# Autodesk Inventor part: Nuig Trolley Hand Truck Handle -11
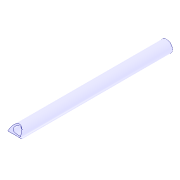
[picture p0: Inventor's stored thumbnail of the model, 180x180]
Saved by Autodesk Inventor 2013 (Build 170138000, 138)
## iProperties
Shininess: 64.0
Length Units: 11269
Angle Units: 11279
Time Units: 11290
Mass Units: 11286
Length Display Precision: 3
Angle Display Precision: 2
Created: 2002-08
Part Number: Nuig Trolley Hand Truck Handle -11
Document SubType Name: Modeling
Designer: kalamea
Material: Generic
Density: 1 g/cm^3
Mass: 71.0808 g
Surface Area: 453.829 cm^2
Volume: 71.0808 cm^3
Density: 0.0
Volumn: 0.0
Area: 0.0
PropertySet Name: Model Information
Control State: 0
Master: False
Checked Out: False
DRAWING NUMBER: ME09-2007-PT
Author: kalamea
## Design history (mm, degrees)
sketch "Sketch1"
  geometry: C1 r 12.7 at (0, 0); C2 r 9.525 at (0, 0); 1 further point
  constraints: 2 centre point, 2 coincident
  dimensions: "d0" = 19.05 diameter of C2; "d1" = 25.4 diameter of C1
extrude "Extrusion1" new body sketch "Sketch1" distance "d2" = 330.2; taper "d3" = 0 deg
workaxis "Work Axis1"
workplane "Work Plane1"
sketch "Sketch3"
  geometry: L1 (-12.7, 330.2)-(12.7, 330.2) reference; L2 (12.7, 330.2)-(-12.7, 330.2); A1 r 12.7 centre (0, 330.2) between (-12.7, 330.2) and (12.7, 330.2)
  constraints: 2 end point, 2 point on circle, 2 point on line, 1 centre point, 1 midpoint
  dimensions: "d10" = 12.7 radius of A1; "d11" = 0 distance of L2.end L1.start
extrude "Extrusion3" cut sketch "Sketch3" stored distance "d12" = 25.4; taper "d13" = 0 deg
body "Solid1"
other parameters: "d4" = 0
